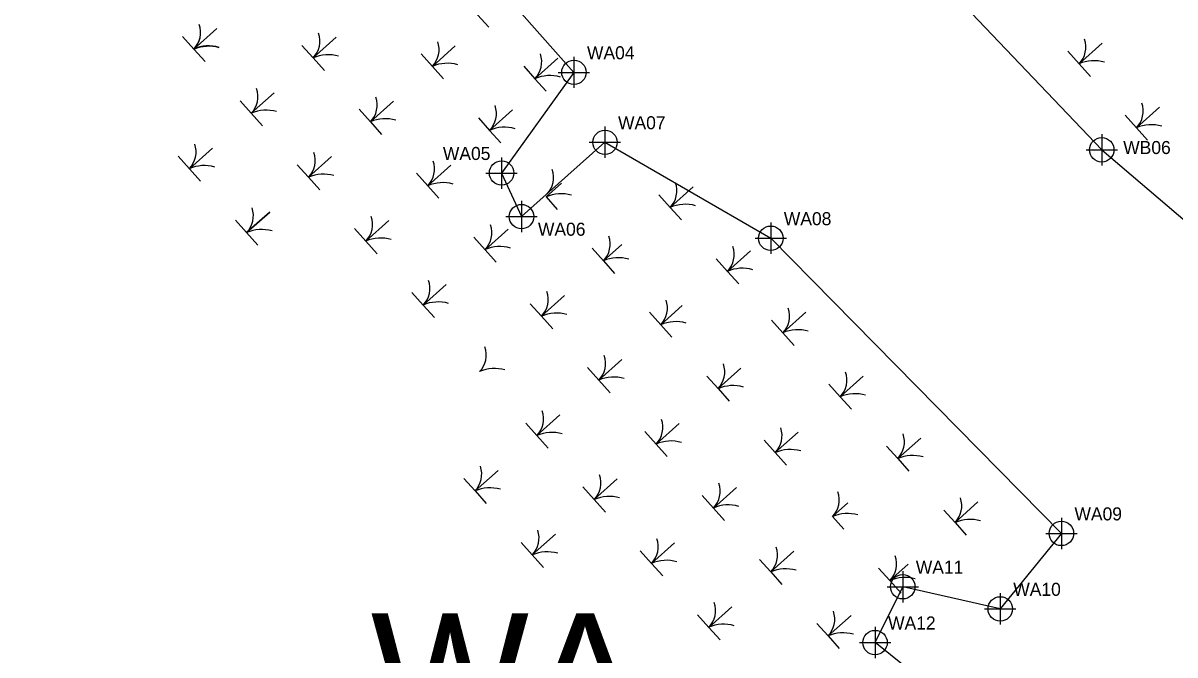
# Model space of a CAD drawing. Extents: x 2126502 to 2127032, y 149550 to 150101.
# Drawn here: x 2126527.8 to 2126748.5, y 149784.8 to 149905.9 of the extents above; entities that cross this region are included whole.
import ezdxf

# ---------------------------------------------------------------- set-up
doc = ezdxf.new("R2010")
doc.units = 0
for name, color, linetype in [('Default', 7, 'Continuous'), ('Exist Environmental Wetland Boundary', 7, 'Continuous'), ('Exist Environmental Wetland Boundary Cogo Number', 7, 'Continuous'), ('Exist Environmental Wetland Boundary Cogo Point CELL', 7, 'Continuous'), ('Exist Hydro Swamp or Marsh', 7, 'Continuous')]:
    doc.layers.add(name, color=color, linetype=linetype)

msp = doc.modelspace()

# ---------------------------------------------------------------- linework, layer by layer
at = {"layer": 'Exist Environmental Wetland Boundary'}
for p, q in [((2126726.71, 149808.11), (2126714.99, 149793.65)), ((2126691.01, 149787.19), (2126696.32, 149797.89)), ((2126714.99, 149793.65), (2126696.32, 149797.89)), ((2126708.85, 149772.96), (2126691.01, 149787.19))]:
    msp.add_line(p, q, dxfattribs=at)
for points in [[(2126558.24, 150042.64), (2126586.56, 150016.72), (2126627.79, 149984.18), (2126669.56, 149945.39), (2126708.19, 149909.19), (2126734.44, 149881.64), (2126779.81, 149842.99), (2126804.06, 149818.21), (2126812.44, 149808.38)], [(2126527.8, 150003.98), (2126555.27, 149971.55), (2126605.73, 149927.65), (2126633.33, 149896.49), (2126619.48, 149877.19), (2126623.29, 149868.84), (2126639.28, 149883.08), (2126671.04, 149864.69), (2126726.71, 149808.11)]]:
    msp.add_lwpolyline(points, dxfattribs=at)
at = {"layer": 'Exist Environmental Wetland Boundary Cogo Point CELL'}
for points in [[(2126633.33, 149899.49), (2126633.33, 149896.49)], [(2126630.33, 149896.49), (2126633.33, 149896.49)], [(2126633.33, 149896.49), (2126636.33, 149896.49)], [(2126633.33, 149896.49), (2126633.33, 149893.49)], [(2126639.28, 149886.08), (2126639.28, 149883.08)], [(2126734.44, 149884.64), (2126734.44, 149881.64)], [(2126636.28, 149883.08), (2126639.28, 149883.08)], [(2126639.28, 149883.08), (2126642.28, 149883.08)], [(2126639.28, 149883.08), (2126639.28, 149880.08)], [(2126731.44, 149881.64), (2126734.44, 149881.64)], [(2126734.44, 149881.64), (2126737.44, 149881.64)], [(2126734.44, 149881.64), (2126734.44, 149878.64)], [(2126619.48, 149880.19), (2126619.48, 149877.19)], [(2126616.48, 149877.19), (2126619.48, 149877.19)], [(2126619.48, 149877.19), (2126622.48, 149877.19)], [(2126619.48, 149877.19), (2126619.48, 149874.19)], [(2126623.29, 149871.84), (2126623.29, 149868.84)], [(2126620.29, 149868.84), (2126623.29, 149868.84)], [(2126623.29, 149868.84), (2126626.29, 149868.84)], [(2126623.29, 149868.84), (2126623.29, 149865.84)], [(2126671.04, 149867.69), (2126671.04, 149864.69)], [(2126668.04, 149864.69), (2126671.04, 149864.69)], [(2126671.04, 149864.69), (2126674.04, 149864.69)], [(2126671.04, 149864.69), (2126671.04, 149861.69)], [(2126726.71, 149811.11), (2126726.71, 149808.11)], [(2126723.71, 149808.11), (2126726.71, 149808.11)], [(2126726.71, 149808.11), (2126729.71, 149808.11)], [(2126726.71, 149808.11), (2126726.71, 149805.11)], [(2126696.32, 149800.89), (2126696.32, 149797.89)], [(2126693.32, 149797.89), (2126696.32, 149797.89)], [(2126696.32, 149797.89), (2126699.32, 149797.89)], [(2126696.32, 149797.89), (2126696.32, 149794.89)], [(2126714.99, 149796.65), (2126714.99, 149793.65)], [(2126711.99, 149793.65), (2126714.99, 149793.65)], [(2126714.99, 149793.65), (2126717.99, 149793.65)], [(2126714.99, 149793.65), (2126714.99, 149790.65)], [(2126691.01, 149790.19), (2126691.01, 149787.19)], [(2126688.01, 149787.19), (2126691.01, 149787.19)], [(2126691.01, 149787.19), (2126694.01, 149787.19)], [(2126691.01, 149787.19), (2126691.01, 149784.19)]]:
    msp.add_lwpolyline(points, dxfattribs=at)
for centre in [(2126633.33, 149896.49), (2126639.28, 149883.08), (2126734.44, 149881.64), (2126619.48, 149877.19), (2126623.29, 149868.84), (2126671.04, 149864.69), (2126726.71, 149808.11), (2126696.32, 149797.89), (2126714.99, 149793.65), (2126691.01, 149787.19)]:
    msp.add_circle(centre, 2.34, dxfattribs=at)
at = {"layer": 'Exist Hydro Swamp or Marsh'}
for points in [[(2126612.74, 149909.93), (2126614.89, 149907.53), (2126619.3, 149911.48), (2126614.89, 149907.53), (2126617.04, 149905.13)], [(2126558.36, 149903.36), (2126560.51, 149900.96), (2126564.92, 149904.91), (2126560.51, 149900.96), (2126562.67, 149898.56)], [(2126581.22, 149901.66), (2126583.37, 149899.26), (2126587.78, 149903.21), (2126583.37, 149899.26), (2126585.53, 149896.86)], [(2126604.05, 149900.03), (2126606.21, 149897.63), (2126610.61, 149901.58), (2126606.21, 149897.63), (2126608.36, 149895.23)], [(2126727.94, 149900.52), (2126730.1, 149898.12), (2126734.5, 149902.07), (2126730.1, 149898.12), (2126732.25, 149895.72)], [(2126623.71, 149897.68), (2126625.87, 149895.27), (2126630.27, 149899.22), (2126625.87, 149895.27), (2126628.02, 149892.87)], [(2126569.37, 149891.04), (2126571.52, 149888.64), (2126575.93, 149892.59), (2126571.52, 149888.64), (2126573.67, 149886.24)], [(2126592.2, 149889.41), (2126594.35, 149887.01), (2126598.76, 149890.96), (2126594.35, 149887.01), (2126596.5, 149884.6)], [(2126738.92, 149888.27), (2126741.07, 149885.86), (2126745.48, 149889.81), (2126741.07, 149885.86), (2126743.23, 149883.46)], [(2126615.03, 149887.78), (2126617.18, 149885.37), (2126621.59, 149889.32), (2126617.18, 149885.37), (2126619.34, 149882.97)], [(2126557.51, 149880.42), (2126559.66, 149878.02), (2126564.07, 149881.97), (2126559.66, 149878.02), (2126561.81, 149875.62)], [(2126580.34, 149878.79), (2126582.49, 149876.39), (2126586.9, 149880.33), (2126582.49, 149876.39), (2126584.65, 149873.98)], [(2126603.18, 149877.16), (2126605.33, 149874.75), (2126609.74, 149878.7), (2126605.33, 149874.75), (2126607.48, 149872.35)], [(2126630.93, 149875.25), (2126628, 149872.62), (2126630.15, 149870.21)], [(2126649.61, 149873), (2126651.76, 149870.6), (2126656.17, 149874.55), (2126651.76, 149870.6), (2126653.91, 149868.2)], [(2126568.49, 149868.17), (2126570.64, 149865.77), (2126575.05, 149869.71), (2126570.64, 149865.77), (2126572.79, 149863.36)], [(2126591.32, 149866.54), (2126593.47, 149864.13), (2126597.88, 149868.08), (2126593.47, 149864.13), (2126595.62, 149861.73)], [(2126614.15, 149864.9), (2126616.31, 149862.5), (2126620.71, 149866.45), (2126616.31, 149862.5), (2126618.46, 149860.1)], [(2126636.82, 149862.77), (2126638.97, 149860.36), (2126642.49, 149863.52)], [(2126642.49, 149863.52), (2126638.97, 149860.36), (2126641.12, 149857.96)], [(2126660.59, 149860.75), (2126662.74, 149858.34), (2126667.15, 149862.29), (2126662.74, 149858.34), (2126664.89, 149855.94)], [(2126602.3, 149854.28), (2126604.45, 149851.88), (2126608.86, 149855.83), (2126604.45, 149851.88), (2126606.6, 149849.48)], [(2126624.96, 149852.14), (2126627.12, 149849.74), (2126631.52, 149853.69), (2126627.12, 149849.74), (2126629.27, 149847.34)], [(2126647.8, 149850.51), (2126649.95, 149848.11), (2126654.05, 149851.78)], [(2126654.05, 149851.78), (2126649.95, 149848.11), (2126652.1, 149845.71)], [(2126671.2, 149848.96), (2126673.35, 149846.56), (2126677.76, 149850.51), (2126673.35, 149846.56), (2126675.5, 149844.16)], [(2126635.94, 149839.89), (2126638.09, 149837.49), (2126642.5, 149841.44), (2126638.09, 149837.49), (2126640.25, 149835.09)], [(2126658.77, 149838.26), (2126660.93, 149835.86), (2126665.33, 149839.81), (2126660.93, 149835.86), (2126663.08, 149833.45)], [(2126682.18, 149836.71), (2126684.33, 149834.3), (2126688.74, 149838.25), (2126684.33, 149834.3), (2126686.48, 149831.9)], [(2126624.09, 149829.27), (2126626.24, 149826.87), (2126630.65, 149830.82), (2126626.24, 149826.87), (2126628.39, 149824.47)], [(2126646.92, 149827.64), (2126649.07, 149825.24), (2126653.48, 149829.18), (2126649.07, 149825.24), (2126651.22, 149822.83)], [(2126669.75, 149826.01), (2126671.9, 149823.6), (2126676.31, 149827.55), (2126671.9, 149823.6), (2126674.06, 149821.2)], [(2126693.2, 149824.86), (2126695.35, 149822.45), (2126699.76, 149826.4), (2126695.35, 149822.45), (2126697.5, 149820.05)], [(2126612.23, 149818.65), (2126614.38, 149816.25), (2126618.79, 149820.2), (2126614.38, 149816.25), (2126616.53, 149813.84)], [(2126635.06, 149817.02), (2126637.21, 149814.61), (2126641.62, 149818.56), (2126637.21, 149814.61), (2126639.37, 149812.21)], [(2126657.9, 149815.38), (2126660.05, 149812.98), (2126664.46, 149816.93), (2126660.05, 149812.98), (2126662.2, 149810.58)], [(2126685.82, 149813.96), (2126682.88, 149811.33), (2126685.03, 149808.93)], [(2126704.17, 149812.6), (2126706.33, 149810.2), (2126710.73, 149814.15), (2126706.33, 149810.2), (2126708.48, 149807.8)], [(2126623.21, 149806.4), (2126625.36, 149803.99), (2126629.77, 149807.94), (2126625.36, 149803.99), (2126627.51, 149801.59)], [(2126646.04, 149804.76), (2126648.19, 149802.36), (2126652.6, 149806.31), (2126648.19, 149802.36), (2126650.34, 149799.96)], [(2126668.87, 149803.13), (2126671.03, 149800.73), (2126675.43, 149804.68), (2126671.03, 149800.73), (2126673.18, 149798.33)], [(2126691.7, 149801.48), (2126693.86, 149799.08), (2126697.37, 149802.23)], [(2126697.37, 149802.23), (2126693.86, 149799.08), (2126696.01, 149796.68)], [(2126657.02, 149792.51), (2126659.17, 149790.11), (2126663.58, 149794.06), (2126659.17, 149790.11), (2126661.32, 149787.71)], [(2126679.85, 149790.86), (2126682, 149788.46), (2126686.41, 149792.41), (2126682, 149788.46), (2126684.15, 149786.05)]]:
    msp.add_lwpolyline(points, dxfattribs=at)
for centre, radius, start, end in [((2126557.2, 149904.16), 4.61, 315.9957, 19.3903), ((2126557.22, 149904.1), 4.61, 315.9957, 19.3903), ((2126580.06, 149902.46), 4.61, 315.9957, 19.3903), ((2126563.38, 149894.35), 7.21, 73.9828, 113.4775), ((2126563.41, 149894.28), 7.21, 73.9828, 113.4775), ((2126602.89, 149900.83), 4.61, 315.9957, 19.3903), ((2126726.78, 149901.32), 4.61, 315.9957, 19.3903), ((2126586.25, 149892.65), 7.21, 73.9828, 113.4775), ((2126622.55, 149898.48), 4.61, 315.9957, 19.3903), ((2126732.97, 149891.51), 7.21, 73.9828, 113.4775), ((2126609.08, 149891.02), 7.21, 73.9828, 113.4775), ((2126628.74, 149888.66), 7.21, 73.9828, 113.4775), ((2126568.2, 149891.84), 4.61, 315.9957, 19.3903), ((2126591.03, 149890.21), 4.61, 315.9957, 19.3903), ((2126613.87, 149888.58), 4.61, 315.9957, 19.3903), ((2126737.76, 149889.07), 4.61, 315.9957, 19.3903), ((2126574.39, 149882.03), 7.21, 73.9828, 113.4775), ((2126597.22, 149880.4), 7.21, 73.9828, 113.4775), ((2126620.06, 149878.76), 7.21, 73.9828, 113.4775), ((2126743.94, 149879.25), 7.21, 73.9828, 113.4775), ((2126556.34, 149881.22), 4.61, 315.9957, 19.3903), ((2126579.18, 149879.59), 4.61, 315.9957, 19.3903), ((2126602.01, 149877.96), 4.61, 315.9957, 19.3903), ((2126562.53, 149871.41), 7.21, 73.9828, 113.4775), ((2126585.37, 149869.77), 7.21, 73.9828, 113.4775), ((2126624.84, 149876.33), 4.61, 315.9957, 19.3903), ((2126608.2, 149868.14), 7.21, 73.9828, 113.4775), ((2126648.44, 149873.8), 4.61, 315.9957, 19.3903), ((2126630.87, 149866.01), 7.21, 73.9828, 113.4775), ((2126567.32, 149868.97), 4.61, 315.9957, 19.3903), ((2126654.63, 149863.99), 7.21, 73.9828, 113.4775), ((2126590.15, 149867.34), 4.61, 315.9957, 19.3903), ((2126573.51, 149859.15), 7.21, 73.9828, 113.4775), ((2126612.99, 149865.7), 4.61, 315.9957, 19.3903), ((2126596.34, 149857.52), 7.21, 73.9828, 113.4775), ((2126635.66, 149863.57), 4.61, 315.9957, 19.3903), ((2126619.18, 149855.89), 7.21, 73.9828, 113.4775), ((2126659.42, 149861.55), 4.61, 315.9957, 19.3903), ((2126641.84, 149853.75), 7.21, 73.9828, 113.4775), ((2126665.61, 149851.73), 7.21, 73.9828, 113.4775), ((2126601.13, 149855.08), 4.61, 315.9957, 19.3903), ((2126607.32, 149845.27), 7.21, 73.9828, 113.4775), ((2126623.8, 149852.95), 4.61, 315.9957, 19.3903), ((2126646.63, 149851.31), 4.61, 315.9957, 19.3903), ((2126629.99, 149843.13), 7.21, 73.9828, 113.4775), ((2126670.03, 149849.76), 4.61, 315.9957, 19.3903), ((2126652.82, 149841.5), 7.21, 73.9828, 113.4775), ((2126676.22, 149839.95), 7.21, 73.9828, 113.4775), ((2126611.94, 149842.33), 4.61, 315.9957, 19.3903), ((2126634.78, 149840.69), 4.61, 315.9957, 19.3903), ((2126618.13, 149832.51), 7.21, 73.9828, 113.4775), ((2126657.61, 149839.06), 4.61, 315.9957, 19.3903), ((2126681.01, 149837.51), 4.61, 315.9957, 19.3903), ((2126640.97, 149830.88), 7.21, 73.9828, 113.4775), ((2126663.8, 149829.24), 7.21, 73.9828, 113.4775), ((2126687.2, 149827.69), 7.21, 73.9828, 113.4775), ((2126622.92, 149830.07), 4.61, 315.9957, 19.3903), ((2126645.75, 149828.44), 4.61, 315.9957, 19.3903), ((2126668.59, 149826.81), 4.61, 315.9957, 19.3903), ((2126629.11, 149820.26), 7.21, 73.9828, 113.4775), ((2126651.94, 149818.62), 7.21, 73.9828, 113.4775), ((2126692.03, 149825.66), 4.61, 315.9957, 19.3903), ((2126674.78, 149816.99), 7.21, 73.9828, 113.4775), ((2126698.22, 149815.84), 7.21, 73.9828, 113.4775), ((2126611.06, 149819.45), 4.61, 315.9957, 19.3903), ((2126633.9, 149817.82), 4.61, 315.9957, 19.3903), ((2126656.73, 149816.19), 4.61, 315.9957, 19.3903), ((2126617.25, 149809.64), 7.21, 73.9828, 113.4775), ((2126640.09, 149808), 7.21, 73.9828, 113.4775), ((2126679.56, 149814.55), 4.61, 315.9957, 19.3903), ((2126703.01, 149813.4), 4.61, 315.9957, 19.3903), ((2126662.92, 149806.37), 7.21, 73.9828, 113.4775), ((2126685.75, 149804.72), 7.21, 73.9828, 113.4775), ((2126709.2, 149803.59), 7.21, 73.9828, 113.4775), ((2126622.04, 149807.2), 4.61, 315.9957, 19.3903), ((2126644.87, 149805.57), 4.61, 315.9957, 19.3903), ((2126628.23, 149797.38), 7.21, 73.9828, 113.4775), ((2126667.71, 149803.93), 4.61, 315.9957, 19.3903), ((2126690.54, 149802.28), 4.61, 315.9957, 19.3903), ((2126651.06, 149795.75), 7.21, 73.9828, 113.4775), ((2126673.9, 149794.12), 7.21, 73.9828, 113.4775), ((2126696.73, 149792.47), 7.21, 73.9828, 113.4775), ((2126655.85, 149793.31), 4.61, 315.9957, 19.3903), ((2126678.68, 149791.66), 4.61, 315.9957, 19.3903), ((2126662.04, 149783.5), 7.21, 73.9828, 113.4775), ((2126684.87, 149781.85), 7.21, 73.9828, 113.4775)]:
    msp.add_arc(centre, radius, start, end, dxfattribs=at)

# ---------------------------------------------------------------- texts
at = {"layer": 'Default'}
msp.add_text('WA', height=24, dxfattribs=at).set_placement((2126594.42, 149768.79))
at = {"layer": 'Exist Environmental Wetland Boundary Cogo Number'}
for s, p in [('WA04', (2126635.83, 149898.99)), ('WA07', (2126641.78, 149885.58)), ('WB06', (2126738.55, 149880.83)), ('WA05', (2126608.23, 149879.69)), ('WA08', (2126673.54, 149867.19)), ('WA06', (2126626.44, 149865.17)), ('WA09', (2126729.21, 149810.61)), ('WA11', (2126698.82, 149800.39)), ('WA10', (2126717.49, 149796.15)), ('WA12', (2126693.51, 149789.69))]:
    msp.add_text(s, height=2.5, dxfattribs=at).set_placement(p)

doc.saveas('drawing.dxf')
